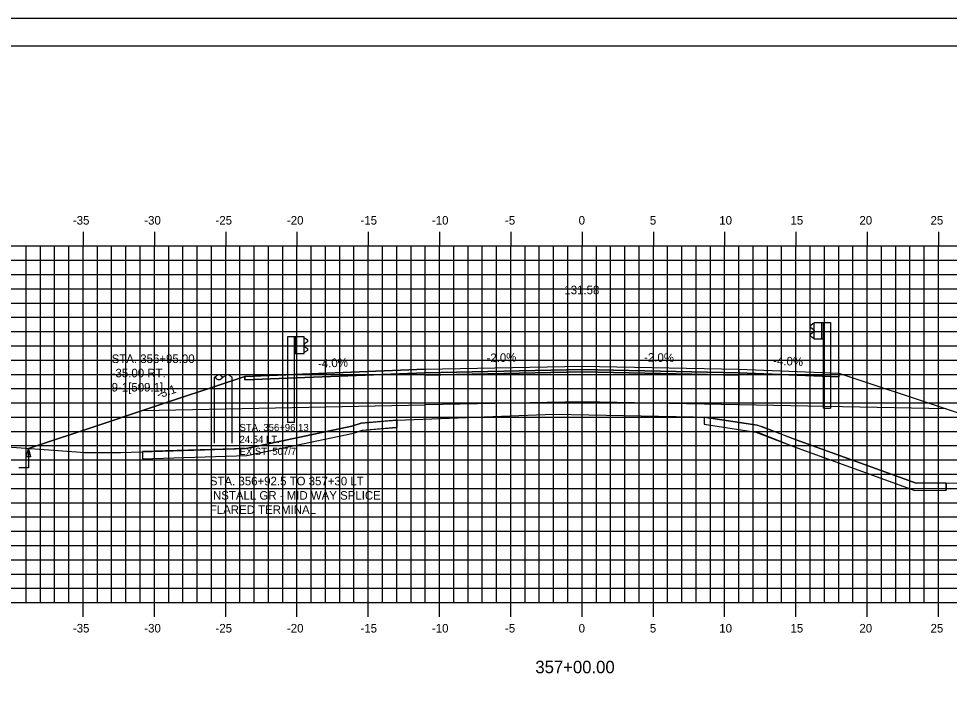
# Model space of a CAD drawing. Extents: x 1145638 to 1145808, y 608981 to 609091.
# Drawn here: x 1145681.1 to 1145746.4, y 609044.5 to 609091.3 of the extents above; entities that cross this region are included whole.
import ezdxf

# ---------------------------------------------------------------- set-up
doc = ezdxf.new("R2010")
doc.units = 0
for name, color, linetype in [('ANNOTATION', 7, 'Continuous'), ('BORDER', 7, 'Continuous'), ('D_Guardrail_Beam_Lt', 7, 'Continuous'), ('D_Guardrail_Beam_Rt', 7, 'Continuous'), ('D_Guardrail_ConcBarrier', 7, 'Continuous'), ('D_Roadway_Centerline', 7, 'Continuous'), ('D_Roadway_Centerline_Text', 7, 'Continuous'), ('D_Roadway_Edge_Shoulder', 7, 'Continuous'), ('D_Roadway_Edge_TW', 7, 'Continuous'), ('D_Roadway_Pavement', 7, 'Continuous'), ('D_Roadway_SlopeLines', 7, 'Continuous'), ('D_Roadway_SubGrade', 7, 'Continuous'), ('D_Text_Monospaced', 7, 'Continuous'), ('D_Text_Standard', 7, 'Continuous'), ('H_V ANNOTATION', 7, 'Continuous'), ('MAJOR', 7, 'Continuous'), ('MINOR', 7, 'Continuous'), ('PLOT BOUNDARY', 7, 'Continuous'), ('S_Roadway_Centerline', 7, 'Continuous'), ('S_Utilities_Pole_Power', 7, 'Continuous'), ('SHADING', 7, 'Continuous')]:
    doc.layers.add(name, color=color, linetype=linetype)

msp = doc.modelspace()

# ---------------------------------------------------------------- linework, layer by layer
msp.add_lwpolyline([(1145681.816, 609061.135), (1145686.815, 609062.801), (1145689.815, 609063.801), (1145696.986, 609066.192), (1145696.987, 609066.192), (1145709.645, 609066.698), (1145720.645, 609066.918), (1145731.645, 609066.698), (1145738.645, 609066.418), (1145746.177, 609063.907), (1145749.177, 609062.907), (1145764.157, 609057.914)])
at = {"layer": 'BORDER'}
msp.add_lwpolyline([(1145645.645, 608984.335), (1145805.645, 608984.335), (1145805.645, 609089.335), (1145645.645, 609089.335)], close=True, dxfattribs=at)
at = {"layer": 'D_Guardrail_Beam_Lt'}
for p, q in [((1145699.983, 609068.966), (1145699.983, 609062.966)), ((1145700.454, 609068.966), (1145699.983, 609068.966)), ((1145701.141, 609068.966), (1145700.454, 609068.966)), ((1145700.454, 609068.966), (1145700.454, 609067.799)), ((1145700.516, 609068.966), (1145700.516, 609067.799)), ((1145700.62, 609068.966), (1145700.62, 609067.799)), ((1145701.141, 609067.799), (1145701.141, 609068.966)), ((1145701.141, 609068.882), (1145701.215, 609068.868)), ((1145701.375, 609068.618), (1145701.179, 609068.482)), ((1145701.231, 609068.861), (1145701.375, 609068.761)), ((1145701.146, 609068.418), (1145701.146, 609068.347)), ((1145701.179, 609068.283), (1145701.375, 609068.147)), ((1145701.375, 609068.004), (1145701.231, 609067.904)), ((1145700.454, 609067.799), (1145701.141, 609067.799)), ((1145700.474, 609062.966), (1145700.474, 609067.799)), ((1145701.215, 609067.897), (1145701.141, 609067.882)), ((1145700.474, 609062.966), (1145699.983, 609062.966))]:
    msp.add_line(p, q, dxfattribs=at)
for centre, major_axis, start_param, end_param in [((1145701.207, 609068.827), (0.0417, 0), 0.959931, 1.376053), ((1145701.324, 609068.69), (0.0877, 0), 5.323254, 7.243116), ((1145701.225, 609068.418), (-0.0789, 0), 5.323254, 6.283185), ((1145701.225, 609068.347), (-0.0789, 0), 6.283185, 7.243116), ((1145701.324, 609068.075), (0.0877, 0), 5.323254, 7.243116), ((1145701.207, 609067.938), (0.0417, 0), 4.907132, 5.323254)]:
    msp.add_ellipse(centre, major_axis=major_axis, ratio=0.995501, start_param=start_param, end_param=end_param, dxfattribs=at)
at = {"layer": 'D_Guardrail_Beam_Rt'}
for p, q in [((1145736.831, 609069.868), (1145736.688, 609069.768)), ((1145736.688, 609069.625), (1145736.883, 609069.489)), ((1145736.883, 609069.29), (1145736.688, 609069.154)), ((1145736.921, 609069.889), (1145736.847, 609069.875)), ((1145736.917, 609069.424), (1145736.917, 609069.354)), ((1145736.688, 609069.01), (1145736.831, 609068.91)), ((1145736.847, 609068.904), (1145736.921, 609068.889))]:
    msp.add_line(p, q, dxfattribs=at)
for centre, major_axis, start_param, end_param in [((1145736.738, 609069.696), (-0.0877, 0), 5.323254, 7.243116), ((1145736.855, 609069.834), (-0.0417, 0), 4.907132, 5.323254), ((1145736.838, 609069.424), (0.0789, 0), 0, 0.959931), ((1145736.838, 609069.354), (0.0789, 0), 5.323254, 6.283185), ((1145736.738, 609069.082), (-0.0877, 0), 5.323254, 7.243116), ((1145736.855, 609068.944), (-0.0417, 0), 0.959931, 1.376053)]:
    msp.add_ellipse(centre, major_axis=major_axis, ratio=0.995501, start_param=start_param, end_param=end_param, dxfattribs=at)
at = {"layer": 'D_Guardrail_ConcBarrier'}
for p, q in [((1145736.921, 609069.973), (1145737.609, 609069.973)), ((1145736.921, 609068.806), (1145736.921, 609069.973)), ((1145737.442, 609069.973), (1145737.442, 609068.806)), ((1145737.546, 609069.973), (1145737.546, 609068.806)), ((1145737.609, 609069.973), (1145738.08, 609069.973)), ((1145737.609, 609069.973), (1145737.609, 609068.806)), ((1145738.08, 609069.973), (1145738.08, 609063.973)), ((1145737.609, 609068.806), (1145736.921, 609068.806)), ((1145737.588, 609063.973), (1145737.588, 609068.806)), ((1145737.588, 609063.973), (1145738.08, 609063.973))]:
    msp.add_line(p, q, dxfattribs=at)
at = {"layer": 'D_Roadway_Edge_Shoulder'}
for points in [[(1145709.645, 609066.698), (1145696.987, 609066.192), (1145696.987, 609065.942), (1145709.645, 609066.448)], [(1145731.645, 609066.698), (1145738.645, 609066.418), (1145738.645, 609066.168), (1145731.645, 609066.448)]]:
    msp.add_lwpolyline(points, close=True, dxfattribs=at)
at = {"layer": 'D_Roadway_Edge_TW'}
msp.add_lwpolyline([(1145709.645, 609066.448), (1145709.645, 609066.698), (1145720.645, 609066.918), (1145731.645, 609066.698), (1145731.645, 609066.448), (1145720.645, 609066.668)], close=True, dxfattribs=at)
at = {"layer": 'D_Roadway_Pavement'}
msp.add_lwpolyline([(1145709.645, 609066.281), (1145709.645, 609066.448), (1145720.645, 609066.668), (1145731.645, 609066.448), (1145731.645, 609066.281), (1145720.645, 609066.501)], close=True, dxfattribs=at)
at = {"layer": 'D_Roadway_SlopeLines'}
for points in [[(1145689.815, 609063.801), (1145686.815, 609062.801)], [(1145746.177, 609063.907), (1145749.177, 609062.907)], [(1145686.815, 609062.801), (1145681.816, 609061.135)]]:
    msp.add_lwpolyline(points, dxfattribs=at)
at = {"layer": 'D_Roadway_SubGrade'}
for p, q in [((1145707.651, 609063.114), (1145707.651, 609062.614)), ((1145729.217, 609063.34), (1145729.217, 609062.84)), ((1145689.815, 609060.915), (1145689.815, 609060.415)), ((1145746.177, 609058.708), (1145746.177, 609058.209))]:
    msp.add_line(p, q, dxfattribs=at)
for points in [[(1145709.645, 609066.281), (1145709.645, 609066.448), (1145696.987, 609065.942), (1145696.987, 609066.192), (1145696.986, 609066.192), (1145689.815, 609063.801), (1145709.645, 609064.198)], [(1145709.645, 609064.198), (1145709.645, 609066.281), (1145720.645, 609066.501), (1145731.645, 609066.281), (1145731.645, 609064.198), (1145720.645, 609064.418)], [(1145731.645, 609066.281), (1145731.645, 609066.448), (1145738.645, 609066.168), (1145738.645, 609066.418), (1145738.645, 609066.418), (1145746.177, 609063.907), (1145731.645, 609064.198)]]:
    msp.add_lwpolyline(points, close=True, dxfattribs=at)
for points in [[(1145729.217, 609062.835), (1145732.845, 609062.275), (1145733.065, 609062.23), (1145735.482, 609061.272), (1145743.99, 609058.2), (1145746.177, 609058.209)], [(1145689.815, 609060.415), (1145697.132, 609060.644), (1145704.618, 609062.22), (1145705.243, 609062.422), (1145707.338, 609062.598), (1145707.4, 609062.607), (1145707.651, 609062.615)]]:
    msp.add_lwpolyline(points, dxfattribs=at)
at = {"layer": 'D_Text_Standard'}
msp.add_lwpolyline([(1145681.816, 609061.135), (1145681.817, 609059.783), (1145681.137, 609059.783)], dxfattribs=at)
msp.add_lwpolyline([(1145681.816, 609061.135), (1145681.962, 609060.553), (1145681.671, 609060.552)], close=True, dxfattribs=at)
at = {"layer": 'MAJOR'}
for p, q in [((1145685.645, 609076.337), (1145685.645, 609075.335)), ((1145690.645, 609076.337), (1145690.645, 609075.335)), ((1145695.645, 609076.337), (1145695.645, 609075.335)), ((1145700.645, 609076.337), (1145700.645, 609075.335)), ((1145705.645, 609076.337), (1145705.645, 609075.335)), ((1145710.645, 609076.337), (1145710.645, 609075.335)), ((1145715.645, 609076.337), (1145715.645, 609075.335)), ((1145720.645, 609076.337), (1145720.645, 609075.335)), ((1145725.645, 609076.337), (1145725.645, 609075.335)), ((1145730.645, 609076.337), (1145730.645, 609075.335)), ((1145735.645, 609076.337), (1145735.645, 609075.335)), ((1145740.645, 609076.337), (1145740.645, 609075.335)), ((1145745.645, 609076.337), (1145745.645, 609075.335)), ((1145650.645, 609075.335), (1145790.645, 609075.335)), ((1145650.645, 609075.335), (1145790.645, 609075.335)), ((1145685.645, 609050.335), (1145685.645, 609075.335)), ((1145690.645, 609050.335), (1145690.645, 609075.335)), ((1145695.645, 609050.335), (1145695.645, 609075.335)), ((1145700.645, 609050.335), (1145700.645, 609075.335)), ((1145705.645, 609050.335), (1145705.645, 609075.335)), ((1145710.645, 609050.335), (1145710.645, 609075.335)), ((1145715.645, 609050.335), (1145715.645, 609075.335)), ((1145720.645, 609050.335), (1145720.645, 609075.335)), ((1145725.645, 609050.335), (1145725.645, 609075.335)), ((1145730.645, 609050.335), (1145730.645, 609075.335)), ((1145735.645, 609050.335), (1145735.645, 609075.335)), ((1145740.645, 609050.335), (1145740.645, 609075.335)), ((1145745.645, 609050.335), (1145745.645, 609075.335)), ((1145650.645, 609070.335), (1145790.645, 609070.335)), ((1145650.645, 609065.335), (1145790.645, 609065.335)), ((1145650.645, 609060.335), (1145790.645, 609060.335)), ((1145650.645, 609055.335), (1145790.645, 609055.335)), ((1145650.645, 609050.335), (1145790.645, 609050.335)), ((1145650.645, 609050.335), (1145790.645, 609050.335)), ((1145685.645, 609049.333), (1145685.645, 609050.335)), ((1145690.645, 609049.333), (1145690.645, 609050.335)), ((1145695.645, 609049.333), (1145695.645, 609050.335)), ((1145700.645, 609049.333), (1145700.645, 609050.335)), ((1145705.645, 609049.333), (1145705.645, 609050.335)), ((1145710.645, 609049.333), (1145710.645, 609050.335)), ((1145715.645, 609049.333), (1145715.645, 609050.335)), ((1145720.645, 609049.333), (1145720.645, 609050.335)), ((1145725.645, 609049.333), (1145725.645, 609050.335)), ((1145730.645, 609049.333), (1145730.645, 609050.335)), ((1145735.645, 609049.333), (1145735.645, 609050.335)), ((1145740.645, 609049.333), (1145740.645, 609050.335)), ((1145745.645, 609049.333), (1145745.645, 609050.335))]:
    msp.add_line(p, q, dxfattribs=at)
at = {"layer": 'MINOR'}
for p, q in [((1145681.645, 609050.335), (1145681.645, 609075.335)), ((1145682.645, 609050.335), (1145682.645, 609075.335)), ((1145683.645, 609050.335), (1145683.645, 609075.335)), ((1145684.645, 609050.335), (1145684.645, 609075.335)), ((1145686.645, 609050.335), (1145686.645, 609075.335)), ((1145687.645, 609050.335), (1145687.645, 609075.335)), ((1145688.645, 609050.335), (1145688.645, 609075.335)), ((1145689.645, 609050.335), (1145689.645, 609075.335)), ((1145691.645, 609050.335), (1145691.645, 609075.335)), ((1145692.645, 609050.335), (1145692.645, 609075.335)), ((1145693.645, 609050.335), (1145693.645, 609075.335)), ((1145694.645, 609050.335), (1145694.645, 609075.335)), ((1145696.645, 609050.335), (1145696.645, 609075.335)), ((1145697.645, 609050.335), (1145697.645, 609075.335)), ((1145698.645, 609050.335), (1145698.645, 609075.335)), ((1145699.645, 609050.335), (1145699.645, 609075.335)), ((1145701.645, 609050.335), (1145701.645, 609075.335)), ((1145702.645, 609050.335), (1145702.645, 609075.335)), ((1145703.645, 609050.335), (1145703.645, 609075.335)), ((1145704.645, 609050.335), (1145704.645, 609075.335)), ((1145706.645, 609050.335), (1145706.645, 609075.335)), ((1145707.645, 609050.335), (1145707.645, 609075.335)), ((1145708.645, 609050.335), (1145708.645, 609075.335)), ((1145709.645, 609050.335), (1145709.645, 609075.335)), ((1145711.645, 609050.335), (1145711.645, 609075.335)), ((1145712.645, 609050.335), (1145712.645, 609075.335)), ((1145713.645, 609050.335), (1145713.645, 609075.335)), ((1145714.645, 609050.335), (1145714.645, 609075.335)), ((1145716.645, 609050.335), (1145716.645, 609075.335)), ((1145717.645, 609050.335), (1145717.645, 609075.335)), ((1145718.645, 609050.335), (1145718.645, 609075.335)), ((1145719.645, 609050.335), (1145719.645, 609075.335)), ((1145721.645, 609050.335), (1145721.645, 609075.335)), ((1145722.645, 609050.335), (1145722.645, 609075.335)), ((1145723.645, 609050.335), (1145723.645, 609075.335)), ((1145724.645, 609050.335), (1145724.645, 609075.335)), ((1145726.645, 609050.335), (1145726.645, 609075.335)), ((1145727.645, 609050.335), (1145727.645, 609075.335)), ((1145728.645, 609050.335), (1145728.645, 609075.335)), ((1145729.645, 609050.335), (1145729.645, 609075.335)), ((1145731.645, 609050.335), (1145731.645, 609075.335)), ((1145732.645, 609050.335), (1145732.645, 609075.335)), ((1145733.645, 609050.335), (1145733.645, 609075.335)), ((1145734.645, 609050.335), (1145734.645, 609075.335)), ((1145736.645, 609050.335), (1145736.645, 609075.335)), ((1145737.645, 609050.335), (1145737.645, 609075.335)), ((1145738.645, 609050.335), (1145738.645, 609075.335)), ((1145739.645, 609050.335), (1145739.645, 609075.335)), ((1145741.645, 609050.335), (1145741.645, 609075.335)), ((1145742.645, 609050.335), (1145742.645, 609075.335)), ((1145743.645, 609050.335), (1145743.645, 609075.335)), ((1145744.645, 609050.335), (1145744.645, 609075.335)), ((1145650.645, 609074.335), (1145790.645, 609074.335)), ((1145650.645, 609073.335), (1145790.645, 609073.335)), ((1145650.645, 609072.335), (1145790.645, 609072.335)), ((1145650.645, 609071.335), (1145790.645, 609071.335)), ((1145650.645, 609069.335), (1145790.645, 609069.335)), ((1145650.645, 609068.335), (1145790.645, 609068.335)), ((1145650.645, 609067.335), (1145790.645, 609067.335)), ((1145650.645, 609066.335), (1145790.645, 609066.335)), ((1145650.645, 609064.335), (1145790.645, 609064.335)), ((1145650.645, 609063.335), (1145790.645, 609063.335)), ((1145650.645, 609062.335), (1145790.645, 609062.335)), ((1145650.645, 609061.335), (1145790.645, 609061.335)), ((1145650.645, 609059.335), (1145790.645, 609059.335)), ((1145650.645, 609058.335), (1145790.645, 609058.335)), ((1145650.645, 609057.335), (1145790.645, 609057.335)), ((1145650.645, 609056.335), (1145790.645, 609056.335)), ((1145650.645, 609054.335), (1145790.645, 609054.335)), ((1145650.645, 609053.335), (1145790.645, 609053.335)), ((1145650.645, 609052.335), (1145790.645, 609052.335)), ((1145650.645, 609051.335), (1145790.645, 609051.335))]:
    msp.add_line(p, q, dxfattribs=at)
at = {"layer": 'PLOT BOUNDARY'}
msp.add_lwpolyline([(1145637.552, 608981.276), (1145807.552, 608981.276), (1145807.552, 609091.276), (1145637.552, 609091.276)], close=True, dxfattribs=at)
at = {"layer": 'S_Roadway_Centerline'}
msp.add_lwpolyline([(1145670.563, 609061.952), (1145685.175, 609060.891), (1145685.737, 609060.851), (1145688.296, 609060.867), (1145697.073, 609061.142), (1145704.489, 609062.703), (1145705.144, 609062.915), (1145707.28, 609063.094), (1145707.355, 609063.105), (1145707.651, 609063.114), (1145718.66, 609063.546), (1145728.46, 609063.36), (1145729.217, 609063.34), (1145732.934, 609062.767), (1145733.208, 609062.71), (1145735.659, 609061.739), (1145744.076, 609058.7), (1145752.065, 609058.73), (1145764.42, 609057.896), (1145765.193, 609057.913)], dxfattribs=at)
at = {"layer": 'S_Utilities_Pole_Power'}
for p, q in [((1145694.851, 609066.132), (1145695.008, 609066.242)), ((1145694.851, 609061.512), (1145694.855, 609066.132)), ((1145695.008, 609066.021), (1145694.851, 609066.132)), ((1145695.32, 609066.242), (1145695.477, 609066.132)), ((1145695.477, 609066.132), (1145695.32, 609066.021)), ((1145695.633, 609066.242), (1145695.477, 609066.132)), ((1145696.101, 609066.132), (1145695.945, 609066.242)), ((1145696.101, 609061.512), (1145696.105, 609066.132))]:
    msp.add_line(p, q, dxfattribs=at)
for centre, start, end in [((1145695.164, 609066.021), 90, 125.26439), ((1145695.164, 609066.242), 234.73561, 270), ((1145695.164, 609066.021), 54.73561, 90), ((1145695.164, 609066.242), 270, 305.26439), ((1145695.789, 609066.021), 90, 125.26439), ((1145695.789, 609066.021), 54.73561, 90)]:
    msp.add_arc(centre, 0.271, start, end, dxfattribs=at)
at = {"layer": 'SHADING'}
for p, q in [((1145707.651, 609062.614), (1145707.651, 609063.114)), ((1145729.217, 609063.34), (1145729.217, 609062.84)), ((1145689.815, 609060.915), (1145689.815, 609060.415)), ((1145746.177, 609058.708), (1145744.076, 609058.7)), ((1145746.177, 609058.209), (1145746.177, 609058.708))]:
    msp.add_line(p, q, dxfattribs=at)
for points in [[(1145707.651, 609063.114), (1145705.144, 609062.915), (1145704.489, 609062.703), (1145697.073, 609061.142), (1145689.815, 609060.915)], [(1145744.076, 609058.7), (1145735.659, 609061.739), (1145732.934, 609062.767), (1145729.217, 609063.34)], [(1145729.217, 609062.84), (1145732.845, 609062.275), (1145735.482, 609061.272), (1145743.99, 609058.2), (1145746.177, 609058.209)], [(1145689.815, 609060.415), (1145697.132, 609060.644), (1145704.618, 609062.22), (1145705.243, 609062.422), (1145707.651, 609062.614)]]:
    msp.add_lwpolyline(points, dxfattribs=at)

# ---------------------------------------------------------------- texts
at = {"layer": 'ANNOTATION'}
for s, rotation, p in [('-4.0%', 2.29061, (1145702.132, 609066.798)), ('-2.0%', 1.14576, (1145713.948, 609067.184)), ('-2.0%', 358.85424, (1145724.988, 609067.231)), ('-4.0%', 357.70939, (1145734.041, 609067.003)), ('-3:1', 18.43483, (1145690.918, 609064.623))]:
    msp.add_text(s, height=0.6, rotation=rotation, dxfattribs=at).set_placement(p)
for s, p in [('STA. 356+92.5 TO 357+30 LT', (1145694.531, 609058.552)), ('INSTALL GR - MID WAY SPLICE', (1145694.531, 609057.55)), ('FLARED TERMINAL', (1145694.531, 609056.548))]:
    msp.add_text(s, height=0.6, dxfattribs=at).set_placement(p)
at = {"layer": 'D_Roadway_Centerline'}
for s, p in [('C', (1145720.64, 609066.918)), ('L', (1145720.645, 609066.911))]:
    msp.add_text(s, height=0.0146, dxfattribs=at).set_placement(p)
at = {"layer": 'D_Roadway_Centerline_Text'}
msp.add_text('131.58', height=0.6, dxfattribs=at).set_placement((1145719.401, 609071.95))
at = {"layer": 'D_Text_Monospaced'}
for s, height, p in [('STA. 356+96.13', 0.49998, (1145696.615, 609062.359)), ('24.54 LT.', 0.5, (1145696.615, 609061.525)), ('EXIST. 507/7', 0.49998, (1145696.615, 609060.685))]:
    msp.add_text(s, height=height, dxfattribs=at).set_placement(p)
at = {"layer": 'D_Text_Standard'}
for s, p in [('STA. 356+95.00', (1145687.645, 609067.13)), ('-35.00 RT.', (1145687.645, 609066.128)), ('9-1[509.1] ', (1145687.645, 609065.132))]:
    msp.add_text(s, height=0.6, dxfattribs=at).set_placement(p)
at = {"layer": 'H_V ANNOTATION'}
for s, height, p in [('-35', 0.6, (1145684.925, 609076.835)), ('-30', 0.6, (1145689.933, 609076.835)), ('-25', 0.6, (1145694.931, 609076.835)), ('-20', 0.6, (1145699.939, 609076.835)), ('-15', 0.6, (1145705.102, 609076.835)), ('-10', 0.6, (1145710.11, 609076.835)), ('-5', 0.6, (1145715.236, 609076.835)), ('0', 0.6, (1145720.404, 609076.835)), ('5', 0.6, (1145725.396, 609076.835)), ('10', 0.6, (1145730.27, 609076.835)), ('15', 0.6, (1145735.262, 609076.835)), ('20', 0.6, (1145740.099, 609076.835)), ('25', 0.6, (1145745.091, 609076.835)), ('-35', 0.6, (1145684.925, 609048.235)), ('-30', 0.6, (1145689.933, 609048.235)), ('-25', 0.6, (1145694.931, 609048.235)), ('-20', 0.6, (1145699.939, 609048.235)), ('-15', 0.6, (1145705.102, 609048.235)), ('-10', 0.6, (1145710.11, 609048.235)), ('-5', 0.6, (1145715.236, 609048.235)), ('0', 0.6, (1145720.404, 609048.235)), ('5', 0.6, (1145725.396, 609048.235)), ('10', 0.6, (1145730.27, 609048.235)), ('15', 0.6, (1145735.262, 609048.235)), ('20', 0.6, (1145740.099, 609048.235)), ('25', 0.6, (1145745.091, 609048.235)), ('357+00.00', 0.875, (1145717.368, 609045.378))]:
    msp.add_text(s, height=height, dxfattribs=at).set_placement(p)
at = {"layer": 'S_Roadway_Centerline'}
for s, p in [('L', (1145718.652, 609063.538)), ('C', (1145718.655, 609063.546))]:
    msp.add_text(s, height=0.0146, dxfattribs=at).set_placement(p)

doc.saveas('drawing.dxf')
